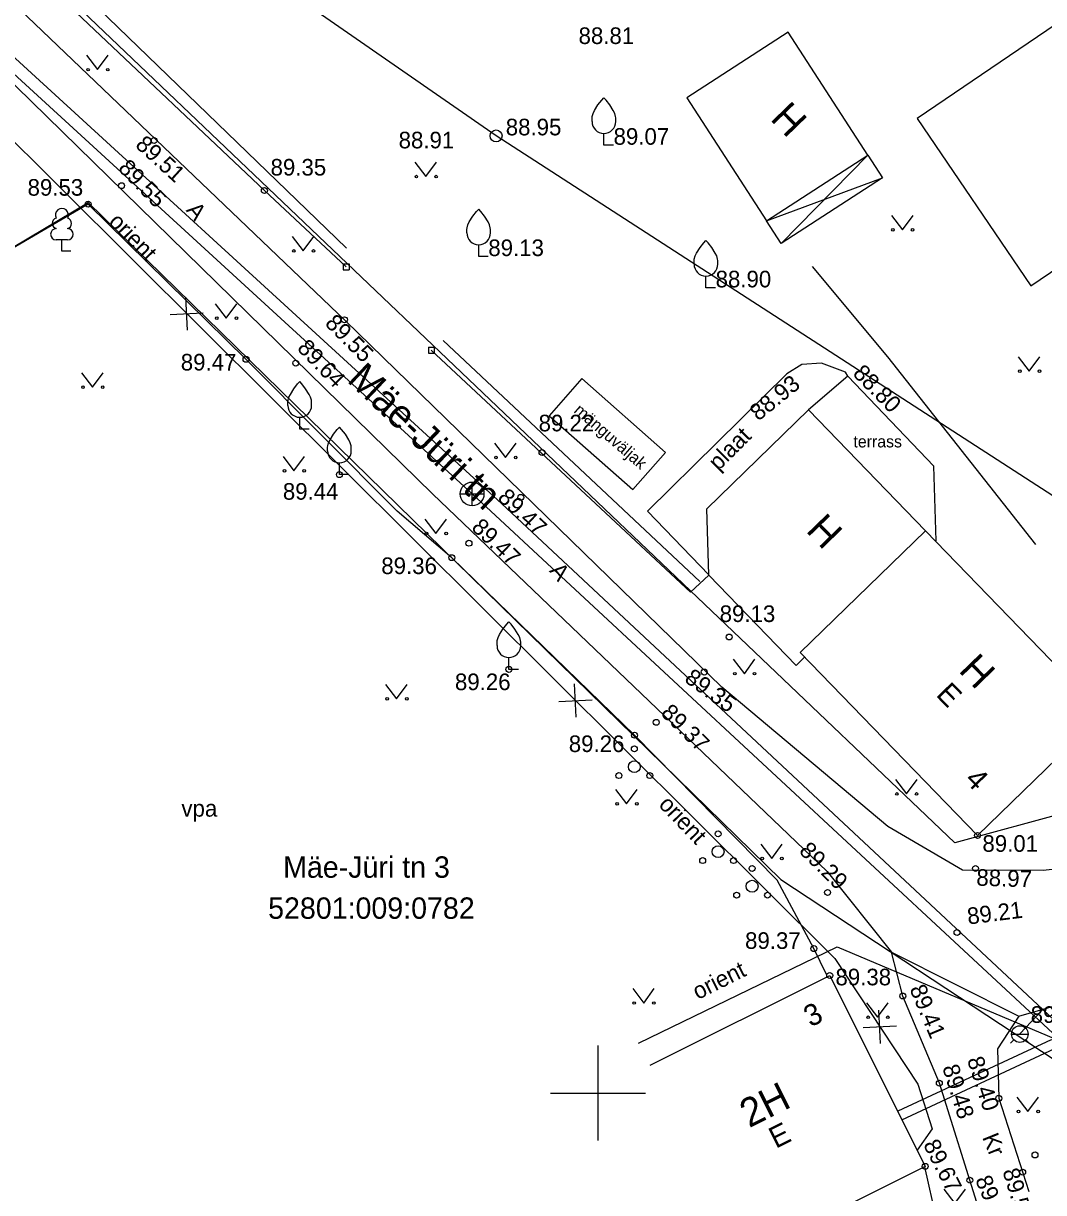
# Model space of a CAD drawing. Extents: x 648748 to 649126, y 6457789 to 6458252.
# Drawn here: x 649025.8 to 649068.77, y 6457945.81 to 6457995.06 of the extents above; entities that cross this region are included whole.
import ezdxf

# ---------------------------------------------------------------- set-up
doc = ezdxf.new("R2010")
doc.units = 0
for name, color, linetype in [('AED', 7, 'Continuous'), ('HALJASTUS', 7, 'Continuous'), ('HOONE', 7, 'Continuous'), ('HOONEDET', 7, 'Continuous'), ('KKAEV', 7, 'Continuous'), ('KORGUS-EH2000', 7, 'Continuous'), ('KTRASS', 7, 'Continuous'), ('MPOHULIIN', 7, 'Continuous'), ('PIIR', 7, 'Continuous'), ('POST', 7, 'Continuous'), ('PUU', 7, 'Continuous'), ('RAJATIS', 7, 'Continuous'), ('TEE', 7, 'Continuous'), ('VKAEV', 7, 'Continuous'), ('VORK', 7, 'Continuous'), ('VTRASS', 7, 'Continuous')]:
    doc.layers.add(name, color=color, linetype=linetype)

msp = doc.modelspace()

# ---------------------------------------------------------------- linework, layer by layer
at = {"layer": 'AED'}
for p, q in [((649039.269, 6457984.935), (649039.269, 6457984.685)), ((649039.269, 6457984.935), (649039.519, 6457984.935)), ((649039.269, 6457984.685), (649039.519, 6457984.685)), ((649039.519, 6457984.935), (649039.519, 6457984.685)), ((649042.858, 6457981.426), (649042.858, 6457981.176)), ((649042.858, 6457981.426), (649043.108, 6457981.426)), ((649042.858, 6457981.176), (649043.108, 6457981.176)), ((649043.108, 6457981.426), (649043.108, 6457981.176)), ((649063.752, 6457946.898), (649064.411, 6457944.007))]:
    msp.add_line(p, q, dxfattribs=at)
for points in [[(649031.864, 6458010.925), (649023.216, 6458000.624), (649028.027, 6457995.514), (649035.951, 6457988.021), (649039.394, 6457984.81)], [(649059.627, 6457954.996), (649059.096, 6457956.086), (649057.552, 6457958.972), (649051.542, 6457965.075), (649043.846, 6457972.555), (649041.547, 6457974.517), (649035.179, 6457980.909), (649028.524, 6457987.447), (649022.18, 6457983.741)], [(649054.666, 6457971.817), (649053.896, 6457971.105), (649042.983, 6457981.301)]]:
    msp.add_lwpolyline(points, dxfattribs=at)
at = {"layer": 'HALJASTUS'}
for p, q in [((649028.461, 6457993.719), (649028.924, 6457993.113)), ((649028.924, 6457993.113), (649029.37, 6457993.719)), ((649042.29, 6457989.214), (649042.753, 6457988.607)), ((649042.753, 6457988.607), (649043.199, 6457989.214)), ((649062.366, 6457986.971), (649062.829, 6457986.364)), ((649062.829, 6457986.364), (649063.275, 6457986.971)), ((649037.126, 6457986.082), (649037.589, 6457985.476)), ((649037.589, 6457985.476), (649038.035, 6457986.082)), ((649033.879, 6457983.252), (649034.343, 6457982.645)), ((649034.343, 6457982.645), (649034.788, 6457983.252)), ((649067.707, 6457981.014), (649068.171, 6457980.408)), ((649068.171, 6457980.408), (649068.616, 6457981.014)), ((649028.248, 6457980.343), (649028.711, 6457979.736)), ((649028.711, 6457979.736), (649029.157, 6457980.343)), ((649045.644, 6457977.38), (649046.108, 6457976.774)), ((649046.108, 6457976.774), (649046.553, 6457977.38)), ((649036.735, 6457976.82), (649037.198, 6457976.213)), ((649037.198, 6457976.213), (649037.644, 6457976.82)), ((649042.713, 6457974.178), (649043.177, 6457973.571)), ((649043.177, 6457973.571), (649043.622, 6457974.178)), ((649055.704, 6457968.275), (649056.168, 6457967.668)), ((649056.168, 6457967.668), (649056.613, 6457968.275)), ((649041.058, 6457967.212), (649041.522, 6457966.605)), ((649041.522, 6457966.605), (649041.967, 6457967.212)), ((649062.534, 6457963.208), (649062.997, 6457962.601)), ((649062.997, 6457962.601), (649063.443, 6457963.208)), ((649050.744, 6457962.791), (649051.208, 6457962.184)), ((649051.208, 6457962.184), (649051.653, 6457962.791)), ((649056.858, 6457960.486), (649057.322, 6457959.88)), ((649057.322, 6457959.88), (649057.767, 6457960.486)), ((649051.467, 6457954.401), (649051.931, 6457953.795)), ((649051.931, 6457953.795), (649052.376, 6457954.401)), ((649061.318, 6457953.8), (649061.782, 6457953.193)), ((649061.782, 6457953.193), (649062.227, 6457953.8)), ((649067.653, 6457949.834), (649068.116, 6457949.227)), ((649068.116, 6457949.227), (649068.562, 6457949.834)), ((649064.574, 6457945.953), (649065.038, 6457945.347)), ((649065.038, 6457945.347), (649065.483, 6457945.953))]:
    msp.add_line(p, q, dxfattribs=at)
msp.add_lwpolyline([(649059.026, 6457984.827), (649062.195, 6457981.016), (649068.436, 6457973.11)], dxfattribs=at)
for centre in [(649028.523, 6457993.113), (649029.352, 6457993.113), (649042.352, 6457988.607), (649043.181, 6457988.607), (649062.428, 6457986.364), (649063.257, 6457986.364), (649037.188, 6457985.476), (649038.017, 6457985.476), (649033.942, 6457982.645), (649034.771, 6457982.645), (649067.77, 6457980.408), (649068.599, 6457980.408), (649028.31, 6457979.736), (649029.139, 6457979.736), (649045.707, 6457976.774), (649046.536, 6457976.774), (649036.797, 6457976.213), (649037.626, 6457976.213), (649042.776, 6457973.571), (649043.605, 6457973.571), (649055.767, 6457967.668), (649056.596, 6457967.668), (649041.121, 6457966.605), (649041.95, 6457966.605), (649062.596, 6457962.601), (649063.425, 6457962.601), (649050.807, 6457962.184), (649051.636, 6457962.184), (649056.921, 6457959.88), (649057.75, 6457959.88), (649051.53, 6457953.795), (649052.359, 6457953.795), (649061.381, 6457953.193), (649062.21, 6457953.193), (649067.715, 6457949.227), (649068.544, 6457949.227)]:
    msp.add_circle(centre, 0.055, dxfattribs=at)
at = {"layer": 'HOONE'}
for points in [[(649072.015, 6457996.882), (649063.446, 6457991.053), (649068.243, 6457984.001), (649073.604, 6457987.648), (649075.908, 6457984.326), (649079.415, 6457986.758), (649077.261, 6457989.865)], [(649053.745, 6457991.919), (649057.104, 6457986.742), (649061.376, 6457989.514), (649058.017, 6457994.691), (649053.745, 6457991.919)], [(649061.376, 6457989.514), (649061.993, 6457988.561), (649057.722, 6457985.79), (649057.104, 6457986.742)], [(649058.706, 6457968.366), (649058.349, 6457968.019), (649054.666, 6457971.817), (649054.676, 6457971.827), (649054.592, 6457974.617), (649058.864, 6457978.777), (649063.804, 6457973.681)], [(649058.52, 6457968.558), (649063.804, 6457973.681), (649071.276, 6457965.976), (649065.991, 6457960.854), (649058.52, 6457968.558)], [(649052.2, 6457951.172), (649059.765, 6457954.955), (649063.786, 6457946.915), (649056.221, 6457943.132)]]:
    msp.add_lwpolyline(points, dxfattribs=at)
at = {"layer": 'HOONEDET'}
for points in [[(649057.722, 6457985.79), (649061.376, 6457989.514)], [(649057.104, 6457986.742), (649061.993, 6457988.561)]]:
    msp.add_lwpolyline(points, dxfattribs=at)
at = {"layer": 'KKAEV'}
for p, q in [((649044.701, 6457974.739), (649044.701, 6457975.739)), ((649044.201, 6457975.239), (649045.201, 6457975.239))]:
    msp.add_line(p, q, dxfattribs=at)
msp.add_circle((649044.701, 6457975.239), 0.5, dxfattribs=at)
at = {"layer": 'KORGUS-EH2000'}
for centre in [(649031.304, 6457990.126), (649029.933, 6457988.226), (649035.951, 6457988.021), (649028.524, 6457987.447), (649039.321, 6457982.578), (649035.179, 6457980.909), (649037.272, 6457980.749), (649047.646, 6457976.987), (649039.111, 6457976.053), (649046.752, 6457975.096), (649044.567, 6457973.162), (649043.846, 6457972.555), (649055.529, 6457969.212), (649046.25, 6457967.849), (649054.478, 6457967.737), (649052.458, 6457965.619), (649051.542, 6457965.075), (649065.991, 6457960.854), (649065.905, 6457959.463), (649059.674, 6457958.453), (649065.127, 6457956.767), (649059.096, 6457956.086), (649059.765, 6457954.955), (649062.841, 6457954.089), (649064.382, 6457950.416), (649066.885, 6457949.78), (649063.786, 6457946.915), (649067.893, 6457946.668), (649065.667, 6457946.33)]:
    msp.add_circle(centre, 0.125, dxfattribs=at)
at = {"layer": 'KTRASS'}
for p, q in [((649019.745, 6457998.112), (649044.701, 6457975.239)), ((649044.701, 6457975.239), (649069.563, 6457952.163))]:
    msp.add_line(p, q, dxfattribs=at)
for points in [[(649051.71, 6457952.102), (649060.079, 6457956.155), (649069.563, 6457952.163)], [(649069.563, 6457952.163), (649069.086, 6457952.241), (649062.629, 6457949.241)], [(649062.797, 6457948.879), (649069.254, 6457951.879), (649069.563, 6457952.163)]]:
    msp.add_lwpolyline(points, dxfattribs=at)
at = {"layer": 'MPOHULIIN'}
for p, q in [((649045.712, 6457990.322), (649008.42, 6458016.198)), ((649077.318, 6457969.876), (649045.712, 6457990.322))]:
    msp.add_line(p, q, dxfattribs=at)
at = {"layer": 'PIIR'}
for p, q in [((649065.03, 6457960.54), (649022.96, 6458000.66)), ((649017.67, 6457981.07), (649028.53, 6457987.52)), ((649028.53, 6457987.52), (649057.7, 6457959)), ((649080.95, 6457964.88), (649065.03, 6457960.54)), ((649057.7, 6457959), (649069.26, 6457951.39))]:
    msp.add_line(p, q, dxfattribs=at)
at = {"layer": 'POST'}
msp.add_circle((649045.712, 6457990.322), 0.25, dxfattribs=at)
at = {"layer": 'PUU'}
for p, q in [((649050.253, 6457989.927), (649050.253, 6457990.427)), ((649050.653, 6457989.927), (649050.253, 6457989.927)), ((649027.661, 6457985.942), (649027.181, 6457985.942)), ((649027.421, 6457985.467), (649027.421, 6457985.942)), ((649044.977, 6457985.236), (649044.977, 6457985.736)), ((649027.801, 6457985.467), (649027.421, 6457985.467)), ((649045.377, 6457985.236), (649044.977, 6457985.236)), ((649054.551, 6457983.918), (649054.551, 6457984.418)), ((649054.951, 6457983.918), (649054.551, 6457983.918)), ((649037.439, 6457977.97), (649037.439, 6457978.47)), ((649037.839, 6457977.97), (649037.439, 6457977.97)), ((649039.111, 6457976.053), (649039.111, 6457976.553)), ((649039.511, 6457976.053), (649039.111, 6457976.053)), ((649046.25, 6457967.849), (649046.25, 6457968.349)), ((649046.65, 6457967.849), (649046.25, 6457967.849))]:
    msp.add_line(p, q, dxfattribs=at)
for points in [[(649039.41, 6457985.592), (649023.916, 6458000.565), (649032.315, 6458010.397)], [(649049.753, 6457990.927), (649049.753, 6457991.077), (649049.763, 6457991.142), (649049.798, 6457991.272), (649049.858, 6457991.392), (649050.003, 6457991.627), (649050.163, 6457991.832), (649050.253, 6457991.927)], [(649050.753, 6457990.927), (649050.753, 6457991.077), (649050.743, 6457991.142), (649050.708, 6457991.272), (649050.648, 6457991.392), (649050.503, 6457991.627), (649050.343, 6457991.832), (649050.253, 6457991.927)], [(649044.477, 6457986.236), (649044.477, 6457986.386), (649044.487, 6457986.451), (649044.522, 6457986.581), (649044.582, 6457986.701), (649044.727, 6457986.936), (649044.887, 6457987.141), (649044.977, 6457987.236)], [(649045.477, 6457986.236), (649045.477, 6457986.386), (649045.467, 6457986.451), (649045.432, 6457986.581), (649045.372, 6457986.701), (649045.227, 6457986.936), (649045.067, 6457987.141), (649044.977, 6457987.236)], [(649054.051, 6457984.918), (649054.051, 6457985.068), (649054.061, 6457985.133), (649054.096, 6457985.263), (649054.156, 6457985.383), (649054.301, 6457985.618), (649054.461, 6457985.823), (649054.551, 6457985.918)], [(649055.051, 6457984.918), (649055.051, 6457985.068), (649055.041, 6457985.133), (649055.006, 6457985.263), (649054.946, 6457985.383), (649054.801, 6457985.618), (649054.641, 6457985.823), (649054.551, 6457985.918)], [(649043.482, 6457981.71), (649054.293, 6457971.546)], [(649036.939, 6457978.97), (649036.939, 6457979.12), (649036.949, 6457979.185), (649036.984, 6457979.315), (649037.044, 6457979.435), (649037.189, 6457979.67), (649037.349, 6457979.875), (649037.439, 6457979.97)], [(649037.939, 6457978.97), (649037.939, 6457979.12), (649037.929, 6457979.185), (649037.894, 6457979.315), (649037.834, 6457979.435), (649037.689, 6457979.67), (649037.529, 6457979.875), (649037.439, 6457979.97)], [(649038.611, 6457977.053), (649038.611, 6457977.203), (649038.621, 6457977.268), (649038.656, 6457977.398), (649038.716, 6457977.518), (649038.861, 6457977.753), (649039.021, 6457977.958), (649039.111, 6457978.053)], [(649039.611, 6457977.053), (649039.611, 6457977.203), (649039.601, 6457977.268), (649039.566, 6457977.398), (649039.506, 6457977.518), (649039.361, 6457977.753), (649039.201, 6457977.958), (649039.111, 6457978.053)], [(649045.75, 6457968.849), (649045.75, 6457968.999), (649045.76, 6457969.064), (649045.795, 6457969.194), (649045.855, 6457969.314), (649046, 6457969.549), (649046.16, 6457969.754), (649046.25, 6457969.849)], [(649046.75, 6457968.849), (649046.75, 6457968.999), (649046.74, 6457969.064), (649046.705, 6457969.194), (649046.645, 6457969.314), (649046.5, 6457969.549), (649046.34, 6457969.754), (649046.25, 6457969.849)]]:
    msp.add_lwpolyline(points, dxfattribs=at)
for centre, radius in [((649051.535, 6457964.5), 0.125), ((649051.535, 6457963.75), 0.25), ((649050.885, 6457963.375), 0.125), ((649052.185, 6457963.375), 0.125), ((649055.064, 6457960.92), 0.125), ((649055.064, 6457960.17), 0.25), ((649054.414, 6457959.795), 0.125), ((649055.714, 6457959.795), 0.125), ((649056.494, 6457959.463), 0.125), ((649056.494, 6457958.713), 0.25), ((649055.844, 6457958.338), 0.125), ((649057.144, 6457958.338), 0.125), ((649068.413, 6457947.394), 0.125)]:
    msp.add_circle(centre, radius, dxfattribs=at)
for centre, radius, start, end in [((649050.253, 6457990.927), 0.5, 180, 0), ((649027.421, 6457986.987), 0.277, 332.58, 207.42), ((649027.251, 6457986.639), 0.233, 109.022, 253.142), ((649027.591, 6457986.639), 0.233, 286.851, 70.986), ((649027.183, 6457986.179), 0.238, 90.002, 269.395), ((649027.658, 6457986.179), 0.238, 270.605, 89.998), ((649044.977, 6457986.236), 0.5, 180, 0), ((649054.551, 6457984.918), 0.5, 180, 0), ((649037.439, 6457978.97), 0.5, 180, 0), ((649039.111, 6457977.053), 0.5, 180, 0), ((649046.25, 6457968.849), 0.5, 180, 0)]:
    msp.add_arc(centre, radius, start, end, dxfattribs=at)
at = {"layer": 'RAJATIS'}
for points in [[(649047.945, 6457978.532), (649051.473, 6457975.425), (649052.85, 6457976.989), (649049.322, 6457980.096), (649047.945, 6457978.532)], [(649064.244, 6457973.261), (649064.146, 6457976.414), (649060.531, 6457980.2), (649058.864, 6457978.777)]]:
    msp.add_lwpolyline(points, dxfattribs=at)
at = {"layer": 'TEE'}
for points in [[(649073.892, 6457980.444), (649075.277, 6457978.898), (649074.998, 6457977.546), (649073.91, 6457975.39), (649075.219, 6457973.916), (649077.682, 6457970.841), (649078.634, 6457968.92), (649078.21, 6457966.199), (649076.118, 6457962.885), (649072.987, 6457959.848), (649068.76, 6457959.373), (649065.353, 6457959.385), (649062.208, 6457961.227), (649055.218, 6457967.101), (649039.374, 6457982.53), (649021.477, 6457999.638), (649003.487, 6458020.927), (649002.852, 6458022.042), (649010.237, 6458028.696), (649016.817, 6458021.893)], [(649024.176, 6457993.684), (649043.03, 6457975.251), (649059.66, 6457959.338), (649062.362, 6457955.934), (649067.734, 6457953.234), (649069.68, 6457953.796), (649072.111, 6457953.746), (649080.808, 6457958.747), (649093.109, 6457965.781), (649092.235, 6457967.901), (649088.043, 6457976.952), (649080.877, 6457973.605), (649080.278, 6457975.481), (649079.102, 6457978.684), (649075.883, 6457984.236)], [(649060.531, 6457980.2), (649060.425, 6457980.365), (649059.421, 6457980.751), (649058.588, 6457980.699), (649057.958, 6457980.296), (649052.093, 6457974.509), (649054.676, 6457971.827)], [(649066.034, 6457945.162), (649064.382, 6457950.416), (649062.841, 6457954.089), (649062.362, 6457955.934)], [(649067.734, 6457953.234), (649066.831, 6457951.868), (649066.885, 6457949.78), (649068.158, 6457945.85)]]:
    msp.add_lwpolyline(points, dxfattribs=at)
at = {"layer": 'VKAEV'}
for p, q in [((649067.525, 6457952.239), (649067.385, 6457952.099)), ((649067.422, 6457952.486), (649068.122, 6457952.486)), ((649068.02, 6457952.239), (649068.159, 6457952.099))]:
    msp.add_line(p, q, dxfattribs=at)
msp.add_circle((649067.772, 6457952.486), 0.35, dxfattribs=at)
at = {"layer": 'VORK'}
for p, q in [((649050, 6457952), (649050, 6457948)), ((649048, 6457950), (649052, 6457950))]:
    msp.add_line(p, q, dxfattribs=at)
at = {"layer": 'VTRASS'}
for p, q in [((649032.709, 6457982.134), (649032.641, 6457983.533)), ((649031.976, 6457982.799), (649033.374, 6457982.868)), ((649049.087, 6457965.838), (649049.019, 6457967.236)), ((649048.354, 6457966.503), (649049.752, 6457966.571)), ((649061.908, 6457952.094), (649061.84, 6457953.493)), ((649061.175, 6457952.76), (649062.573, 6457952.828))]:
    msp.add_line(p, q, dxfattribs=at)
for points in [[(648962.245, 6458064.485), (648962.49, 6458064.476), (648963.533, 6458062.388), (648984.937, 6458037.806), (648985.682, 6458036.975), (649020.474, 6457998.164), (649045.944, 6457974.832), (649068.737, 6457953.518), (649069.454, 6457952.848), (649087.021, 6457962.34), (649109.829, 6457974.665)], [(649026.951, 6458018.739), (649024.71, 6457999.32), (649021.448, 6457994.005), (649059.981, 6457955.664), (649063.472, 6457950.371), (649064.082, 6457948.494), (649063.446, 6457947.594)], [(649067.773, 6457952.49), (649068.736, 6457953.519)]]:
    msp.add_lwpolyline(points, dxfattribs=at)

# ---------------------------------------------------------------- texts
at = {"layer": 'HALJASTUS'}
msp.add_text('vpa', height=0.7, dxfattribs=at).set_placement((649032.456, 6457961.645))
at = {"layer": 'HOONE'}
for s, height, rotation, p in [('H', 1.2, 314.1017, (649057.219, 6457991.018)), ('H', 1.2, 314.1017, (649058.723, 6457973.672)), ('H', 1.2, 314.1017, (649065.158, 6457967.78)), ('E', 0.9, 314.1017, (649064.203, 6457966.758)), ('4', 0.9, 314.1017, (649065.408, 6457963.163)), ('3', 0.9, 26.5713, (649058.957, 6457952.761)), ('2H', 1.2, 26.5713, (649056.368, 6457948.52)), ('E', 0.9, 26.5713, (649057.493, 6457947.647))]:
    msp.add_text(s, height=height, rotation=rotation, dxfattribs=at).set_placement(p)
at = {"layer": 'KORGUS-EH2000'}
for s, p in [('88.81', (649049.185, 6457994.193)), ('88.95', (649046.119, 6457990.345)), ('88.91', (649041.606, 6457989.797)), ('89.07', (649050.66, 6457989.95)), ('89.35', (649036.212, 6457988.652)), ('89.53', (649025.976, 6457987.803)), ('89.13', (649045.384, 6457985.259)), ('88.90', (649054.958, 6457983.941)), ('89.47', (649032.429, 6457980.439)), ('89.22', (649047.503, 6457977.876)), ('89.44', (649036.729, 6457974.996)), ('89.36', (649040.876, 6457971.864)), ('89.13', (649055.129, 6457969.844)), ('89.26', (649043.978, 6457966.975)), ('89.26', (649048.774, 6457964.367)), ('89.01', (649066.197, 6457960.164)), ('89.37', (649056.199, 6457956.075)), ('89.38', (649060.007, 6457954.54)), ('89.12', (649068.231, 6457952.958))]:
    msp.add_text(s, height=0.7, dxfattribs=at).set_placement(p)
for s, rotation, p in [('89.51', 317.6574, (649030.474, 6457989.887)), ('89.55', 314.2068, (649029.752, 6457988.921)), ('89.55', 314.8041, (649038.463, 6457982.387)), ('89.64', 313.8698, (649037.293, 6457981.345)), ('88.80', 314.5628, (649060.697, 6457980.272)), ('88.93', 39.014, (649056.758, 6457978.285)), ('89.47', 316.3926, (649045.735, 6457975.031)), ('89.47', 316.2906, (649044.632, 6457973.774)), ('89.35', 324.0929, (649053.601, 6457967.365)), ('89.37', 315.2036, (649052.611, 6457965.968)), ('89.29', 315.2036, (649058.434, 6457960.161)), ('88.97', 358.1947, (649065.932, 6457958.74)), ('89.21', 7.1685, (649065.6, 6457957.099)), ('89.41', 292.7625, (649063.117, 6457954.397)), ('89.40', 287.9453, (649065.541, 6457951.413)), ('89.48', 287.4518, (649064.5, 6457951.086)), ('89.67', 296.5713, (649063.689, 6457947.837)), ('89.52', 287.1027, (649067.035, 6457946.717)), ('89.53', 293.3281, (649065.878, 6457946.352))]:
    msp.add_text(s, height=0.7, rotation=rotation, dxfattribs=at).set_placement(p)
at = {"layer": 'KTRASS'}
msp.add_text('orient', height=0.7, rotation=26.4792, dxfattribs=at).set_placement((649054.206, 6457953.919))
at = {"layer": 'PIIR'}
for s, p in [('Mäe-Jüri tn 3', (649036.741, 6457959.072)), ('52801:009:0782', (649036.109, 6457957.343))]:
    msp.add_text(s, height=0.9, rotation=360, dxfattribs=at).set_placement(p)
at = {"layer": 'RAJATIS'}
msp.add_text('mänguväljak', height=0.5, rotation=319.0865, dxfattribs=at).set_placement((649048.954, 6457978.703))
msp.add_text('terrass', height=0.5, dxfattribs=at).set_placement((649060.764, 6457977.199))
at = {"layer": 'TEE'}
for s, height, rotation, p in [('A', 0.7, 309.6743, (649032.624, 6457987.179)), ('Mäe-Jüri tn', 1.2, 316.6153, (649039.39, 6457979.995)), ('plaat', 0.7, 45.0162, (649055.073, 6457976.183)), ('A', 0.7, 309.6743, (649047.93, 6457971.988)), ('Kr', 0.7, 292.0819, (649066.179, 6457948.14))]:
    msp.add_text(s, height=height, rotation=rotation, dxfattribs=at).set_placement(p)
at = {"layer": 'VTRASS'}
for rotation, p in [(314.5323, (649029.35, 6457986.659)), (313.785, (649052.522, 6457962.12))]:
    msp.add_text('orient', height=0.7, rotation=rotation, dxfattribs=at).set_placement(p)

doc.saveas('drawing.dxf')
